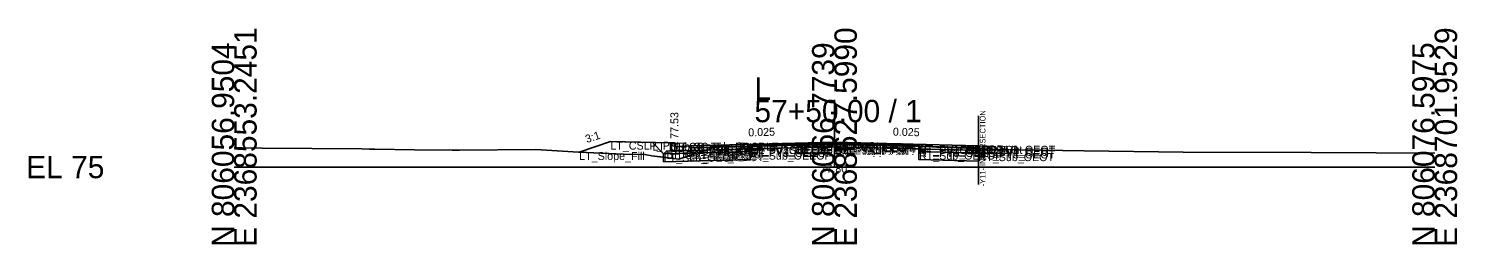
# Model space of a CAD drawing. Extents: x -26 to 8153, y -10 to 9520.
# Drawn here: x 4974.3 to 5152.8, y 5990.3 to 6017.3 of the extents above; entities that cross this region are included whole.
import ezdxf

# ---------------------------------------------------------------- set-up
doc = ezdxf.new("R2010")
doc.units = 0
for name, color, linetype in [('Exist CMT Pavement', 7, 'Continuous'), ('Exist Cross Section Cell', 7, 'Continuous'), ('Exist XS Center Line Elevation Label', 7, 'Continuous'), ('Exist XS Ground Line', 7, 'Continuous'), ('Prop CMT Conc Surface', 7, 'Continuous'), ('Prop CMT Concrete Structures', 7, 'Continuous'), ('Prop CMT Pvmt Course 1', 7, 'Continuous'), ('Prop CMT Pvmt Course 1 CG', 7, 'Continuous'), ('Prop CMT Pvmt Course 1 Wedge', 7, 'Continuous'), ('Prop CMT Pvmt Course 2', 7, 'Continuous'), ('Prop CMT Pvmt Course 2 Wedge', 7, 'Continuous'), ('Prop CMT Pvmt Course 3', 7, 'Continuous'), ('Prop CMT Pvmt Course 3 Wedge', 7, 'Continuous'), ('Prop CMT Pvmt Surface', 7, 'Continuous'), ('Prop CMT Pvmt Wedge Surface 1', 7, 'Continuous'), ('Prop CMT Pvmt Wedge Surface 2', 7, 'Continuous'), ('Prop CMT Pvmt Wedge Surface 3', 7, 'Continuous'), ('Prop CMT Shallow Undercut', 7, 'Continuous'), ('Prop CMT Shallow Undercut Boundary', 7, 'Continuous'), ('Prop CMT Shear Line', 7, 'Continuous'), ('Prop CMT Slope Grass', 7, 'Continuous'), ('Prop CMT Subgrade Earthwork', 7, 'Continuous'), ('Prop XS Earthwork Shape', 7, 'Continuous'), ('Prop XS Hydro Elevations', 7, 'Continuous'), ('Prop XS SE Text', 7, 'Continuous'), ('Prop XS Side Slope Text', 7, 'Continuous'), ('Prop XS Subgrade Earthwork', 7, 'Continuous'), ('Scratch_Level_2', 7, 'Continuous'), ('Scratch_Level_6', 7, 'Continuous')]:
    doc.layers.add(name, color=color, linetype=linetype)

msp = doc.modelspace()

# ---------------------------------------------------------------- linework, layer by layer
at = {"layer": 'Exist CMT Pavement'}
for p, q in [((5064.48, 6002.63), (5066.1, 6002.66)), ((5066.1, 6002.66), (5074.78, 6002.8)), ((5074.78, 6002.8), (5078.73, 6002.77)), ((5078.73, 6002.77), (5085.31, 6002.67))]:
    msp.add_line(p, q, dxfattribs=at)
at = {"layer": 'Exist Cross Section Cell'}
for p, q in [((5075, 6000), (5075, 6008.41)), ((5000, 6000), (5075, 6000)), ((5075, 6000), (5150, 6000))]:
    msp.add_line(p, q, dxfattribs=at)
at = {"layer": 'Exist XS Ground Line'}
for p, q in [((5000, 6002.42), (5000.99, 6002.42)), ((5000.99, 6002.42), (5003.48, 6002.38)), ((5003.48, 6002.38), (5015.93, 6002.26)), ((5058.92, 6002.13), (5060.23, 6002.58)), ((5060.23, 6002.58), (5062.69, 6002.58)), ((5062.69, 6002.58), (5064.48, 6002.63)), ((5064.48, 6002.63), (5066.1, 6002.66)), ((5066.1, 6002.66), (5074.78, 6002.8)), ((5074.78, 6002.8), (5078.73, 6002.77)), ((5078.73, 6002.77), (5085.31, 6002.67)), ((5085.31, 6002.67), (5087.81, 6002.49)), ((5087.81, 6002.49), (5092.95, 6002.31)), ((5092.95, 6002.31), (5095.38, 6002.21)), ((5015.93, 6002.26), (5016.91, 6002.23)), ((5016.91, 6002.23), (5017.57, 6002.22)), ((5017.57, 6002.22), (5022.53, 6002.16)), ((5022.53, 6002.16), (5027.22, 6002.11)), ((5027.22, 6002.11), (5028.16, 6002.11)), ((5028.16, 6002.11), (5037.68, 6002.19)), ((5037.68, 6002.19), (5043.04, 6001.88)), ((5043.04, 6001.88), (5048.64, 6001.63)), ((5048.64, 6001.63), (5051.31, 6001.57)), ((5051.31, 6001.57), (5052.19, 6001.39)), ((5052.19, 6001.39), (5055.56, 6000.99)), ((5055.56, 6000.99), (5058.92, 6002.13)), ((5095.38, 6002.21), (5106.22, 6002.01)), ((5106.22, 6002.01), (5118.56, 6001.88)), ((5118.56, 6001.88), (5134.55, 6001.8)), ((5134.55, 6001.8), (5142.7, 6001.77)), ((5142.7, 6001.77), (5150, 6001.75))]:
    msp.add_line(p, q, dxfattribs=at)
at = {"layer": 'Prop CMT Conc Surface'}
for points in [[(5055, 6002.53), (5055, 6003.03), (5054.5, 6003.03)], [(5057, 6002.66), (5055, 6002.53)]]:
    msp.add_lwpolyline(points, dxfattribs=at)
at = {"layer": 'Prop CMT Concrete Structures'}
for points in [[(5057, 6002.66), (5055, 6002.53), (5055, 6003.03), (5054.5, 6003.03)], [(5054.5, 6003.03), (5054.5, 6002.01), (5057, 6002.07)], [(5057, 6002.07), (5057, 6002.66)]]:
    msp.add_lwpolyline(points, dxfattribs=at)
at = {"layer": 'Prop CMT Pvmt Course 1'}
for points in [[(5075, 6003.11), (5057, 6002.66)], [(5057, 6002.66), (5057, 6002.41)], [(5057, 6002.41), (5064.48, 6002.59)], [(5064.48, 6002.72), (5075, 6002.98)], [(5064.48, 6002.59), (5064.48, 6002.72)], [(5075, 6002.86), (5075, 6003.11)], [(5075, 6003.11), (5093, 6002.66)], [(5075, 6002.86), (5075, 6003.11)], [(5075, 6002.98), (5075, 6002.86), (5075, 6002.86)], [(5085.56, 6002.72), (5075, 6002.98)], [(5075, 6002.98), (5075, 6002.86), (5075, 6002.86)], [(5085.56, 6002.59), (5085.56, 6002.72)], [(5093, 6002.41), (5085.56, 6002.59)], [(5093, 6002.66), (5093, 6002.41)]]:
    msp.add_lwpolyline(points, dxfattribs=at)
at = {"layer": 'Prop CMT Pvmt Course 1 CG'}
for points in [[(5057, 6002.07), (5054, 6002), (5053.66, 6001.66)], [(5053.66, 6001.66), (5057, 6001.74)], [(5057, 6001.74), (5057, 6002.07)]]:
    msp.add_lwpolyline(points, dxfattribs=at)
at = {"layer": 'Prop CMT Pvmt Course 1 Wedge'}
for points in [[(5075, 6002.98), (5064.48, 6002.72)], [(5075, 6002.98), (5085.56, 6002.72)]]:
    msp.add_lwpolyline(points, dxfattribs=at)
at = {"layer": 'Prop CMT Pvmt Course 2'}
for points in [[(5064.48, 6002.59), (5057, 6002.41)], [(5057, 6002.41), (5057, 6002.08)], [(5064.48, 6002.26), (5064.48, 6002.59)], [(5085.56, 6002.26), (5085.56, 6002.59)], [(5085.56, 6002.59), (5093, 6002.41)], [(5093, 6002.41), (5093, 6002.08)], [(5057, 6002.08), (5064.48, 6002.26)], [(5093, 6002.08), (5085.56, 6002.26)]]:
    msp.add_lwpolyline(points, dxfattribs=at)
at = {"layer": 'Prop CMT Pvmt Course 2 Wedge'}
for points in [[(5075, 6002.86), (5064.48, 6002.59)], [(5075, 6002.86), (5085.56, 6002.59)]]:
    msp.add_lwpolyline(points, dxfattribs=at)
at = {"layer": 'Prop CMT Pvmt Course 3'}
for points in [[(5064.48, 6002.26), (5057, 6002.08)], [(5057, 6002.08), (5057, 6001.74)], [(5057, 6001.74), (5064.48, 6001.93)], [(5064.48, 6001.93), (5064.48, 6002.26)], [(5085.56, 6002.26), (5093, 6002.08)], [(5085.56, 6001.93), (5085.56, 6002.26)], [(5093, 6001.74), (5085.56, 6001.93)], [(5093, 6002.08), (5093, 6001.74)]]:
    msp.add_lwpolyline(points, dxfattribs=at)
at = {"layer": 'Prop CMT Pvmt Course 3 Wedge'}
for points in [[(5075, 6002.53), (5064.48, 6002.26)], [(5075, 6002.53), (5085.56, 6002.26)]]:
    msp.add_lwpolyline(points, dxfattribs=at)
at = {"layer": 'Prop CMT Pvmt Surface'}
for points in [[(5075, 6003.11), (5057, 6002.66)], [(5075, 6003.11), (5093, 6002.66), (5093, 6002.31)]]:
    msp.add_lwpolyline(points, dxfattribs=at)
at = {"layer": 'Prop CMT Pvmt Wedge Surface 1'}
for points in [[(5057, 6002.41), (5057, 6002.66)], [(5064.48, 6002.59), (5057, 6002.41)], [(5075, 6002.98), (5064.48, 6002.72)], [(5064.48, 6002.72), (5064.48, 6002.59)], [(5075, 6002.98), (5085.56, 6002.72)], [(5085.56, 6002.72), (5085.56, 6002.59)], [(5085.56, 6002.59), (5093, 6002.41)], [(5093, 6002.41), (5093, 6002.66)]]:
    msp.add_lwpolyline(points, dxfattribs=at)
at = {"layer": 'Prop CMT Pvmt Wedge Surface 2'}
for points in [[(5075, 6002.86), (5057, 6002.41)], [(5057, 6002.41), (5057, 6002.66)], [(5075, 6002.86), (5093, 6002.41)], [(5093, 6002.41), (5093, 6002.66)]]:
    msp.add_lwpolyline(points, dxfattribs=at)
at = {"layer": 'Prop CMT Pvmt Wedge Surface 3'}
for points in [[(5057, 6002.08), (5057, 6002.66)], [(5075, 6002.53), (5057, 6002.08)], [(5075, 6002.53), (5093, 6002.08)], [(5093, 6002.08), (5093, 6002.66)]]:
    msp.add_lwpolyline(points, dxfattribs=at)
at = {"layer": 'Prop CMT Shallow Undercut'}
for p, q in [((5093, 6001.74), (5085.56, 6001.93)), ((5085.56, 6001.93), (5085.56, 6000.93)), ((5085.56, 6000.93), (5093, 6000.74)), ((5093, 6000.74), (5093, 6001.74))]:
    msp.add_line(p, q, dxfattribs=at)
msp.add_lwpolyline([(5053.66, 6001.22), (5053.66, 6000.66), (5064.48, 6000.93), (5064.48, 6001.93), (5057.84, 6001.76), (5055.56, 6000.99)], close=True, dxfattribs=at)
at = {"layer": 'Prop CMT Shallow Undercut Boundary'}
for p, q in [((5053.66, 6001.66), (5053.66, 6000.66)), ((5053.66, 6000.66), (5064.48, 6000.93)), ((5064.48, 6001.93), (5064.48, 6000.93)), ((5085.56, 6001.93), (5085.56, 6000.93)), ((5085.56, 6000.93), (5093, 6000.74)), ((5093, 6001.74), (5093, 6000.74))]:
    msp.add_line(p, q, dxfattribs=at)
at = {"layer": 'Prop CMT Shear Line'}
msp.add_line((5093, 5997.83), (5093, 6006.4), dxfattribs=at)
at = {"layer": 'Prop CMT Slope Grass'}
msp.add_lwpolyline([(5054.5, 6003.03), (5047, 6003.18), (5043.11, 6001.88)], dxfattribs=at)
at = {"layer": 'Prop CMT Subgrade Earthwork'}
for points in [[(5057, 6001.74), (5053.66, 6001.66), (5052.25, 6003.07)], [(5064.48, 6001.93), (5064.49, 6002.63)], [(5085.56, 6001.93), (5085.56, 6002.65)], [(5064.48, 6001.93), (5057, 6001.74)], [(5085.56, 6001.93), (5093, 6001.74)]]:
    msp.add_lwpolyline(points, dxfattribs=at)
at = {"layer": 'Prop XS Earthwork Shape'}
for points in [[(5053.66, 6001.66), (5053.66, 6001.22), (5052.19, 6001.39), (5051.31, 6001.57), (5048.64, 6001.63), (5043.11, 6001.88), (5047, 6003.18), (5052.25, 6003.07)], [(5064.48, 6001.93), (5057.84, 6001.76), (5058.92, 6002.13), (5060.23, 6002.58), (5062.69, 6002.58), (5064.48, 6002.63), (5064.49, 6002.63)], [(5064.48, 6001.93), (5057.84, 6001.76), (5055.56, 6000.99), (5053.66, 6001.22), (5053.66, 6000.66), (5064.48, 6000.93)], [(5057.84, 6001.76), (5057, 6001.74), (5053.66, 6001.66), (5053.66, 6001.22), (5055.56, 6000.99)], [(5085.56, 6001.93), (5085.56, 6000.93), (5093, 6000.74), (5093, 6001.74)], [(5085.56, 6001.93), (5085.56, 6000.93), (5093, 6000.74), (5093, 6001.74)]]:
    msp.add_lwpolyline(points, close=True, dxfattribs=at)
at = {"layer": 'Prop XS Subgrade Earthwork'}
for p, q in [((5053.66, 6001.66), (5064.48, 6001.93)), ((5085.56, 6001.93), (5093, 6001.74))]:
    msp.add_line(p, q, dxfattribs=at)
at = {"layer": 'Scratch_Level_6'}
for p, q in [((5093, 6001.74), (5085.56, 6001.93)), ((5085.56, 6001.93), (5085.56, 6000.93)), ((5085.56, 6000.93), (5093, 6000.74)), ((5093, 6000.74), (5093, 6001.74))]:
    msp.add_line(p, q, dxfattribs=at)
msp.add_lwpolyline([(5053.66, 6001.22), (5053.66, 6000.66), (5064.48, 6000.93), (5064.48, 6001.93), (5057.84, 6001.76), (5055.56, 6000.99)], close=True, dxfattribs=at)

# ---------------------------------------------------------------- texts
at = {"layer": 'Exist Cross Section Cell'}
for s, p in [('E 2368553.2451', (5002.8, 5990)), ('E 2368627.5990', (5077.8, 5990)), ('E 2368701.9529', (5152.8, 5990)), ('N 806056.9504', (5000, 5990)), ('N 806066.7739', (5075, 5990)), ('N 806076.5975', (5150, 5990))]:
    msp.add_text(s, height=2.8, rotation=90, dxfattribs=at).set_placement(p)
for s, p in [('L', (5065, 6008.41)), ('57+50.00 / 1', (5065, 6005.61)), ('EL 75', (4974, 5998.6))]:
    msp.add_text(s, height=2.8, dxfattribs=at).set_placement(p)
at = {"layer": 'Exist XS Center Line Elevation Label'}
msp.add_text('77.80', height=1, dxfattribs=at).set_placement((5073.25, 5999.3))
at = {"layer": 'Prop CMT Shear Line'}
msp.add_text('-Y11- INTERSECTION', height=0.7, rotation=90, dxfattribs=at).set_placement((5093.87, 5997.59))
at = {"layer": 'Prop XS Hydro Elevations'}
msp.add_text('77.53', height=1, rotation=90, dxfattribs=at).set_placement((5055.5, 6003.53))
at = {"layer": 'Prop XS SE Text'}
for rotation, p in [(1.4321, (5064.24, 6003.84)), (358.5679, (5082.29, 6003.93))]:
    msp.add_text('0.025', height=1, rotation=rotation, dxfattribs=at).set_placement(p)
at = {"layer": 'Prop XS Side Slope Text'}
msp.add_text('3:1', height=1, rotation=18.4349, dxfattribs=at).set_placement((5044.06, 6002.99))
at = {"layer": 'Scratch_Level_2'}
for s, p in [('LT_CSLP_Pnt', (5047, 6002.18)), ('LT_Sub_Trench_Out_DLT', (5052.25, 6002.07)), ('LT_CG_Top_BOC', (5054.5, 6002.03)), ('LT_CG_Top_Face', (5055, 6002.03)), ('LT_CG_Top_Gut', (5055, 6001.53)), ('LT_PV1_OEOT', (5057, 6001.66)), ('LT_PV2_OEOT', (5057, 6001.41)), ('LT_PV1_OEEOP', (5064.48, 6001.72)), ('LT_PV_OEEOP_EG', (5064.48, 6001.63)), ('LT_PV2_OEEOP', (5064.48, 6001.59)), ('LT_PV3_OEEOP', (5064.48, 6001.26)), ('LT_PV_Sub_Tie_Out', (5064.49, 6001.63)), ('PV1_PGL', (5075, 6002.11)), ('RT_PV1_IEEOP', (5075, 6001.98)), ('LT_PV1_IEEOP', (5075, 6001.98)), ('RT_PV2_IEEOP', (5075, 6001.86)), ('LT_PV2_IEEOP', (5075, 6001.86)), ('PV2_PGL', (5075, 6001.86)), ('RT_PV_IEEOP_EG', (5075, 6001.8)), ('LT_PV_IEEOP_EG', (5075, 6001.8)), ('RT_PV3_IEEOP', (5075, 6001.53)), ('LT_PV3_IEEOP', (5075, 6001.53)), ('RT_PV_Sub_Tie_Out', (5085.54, 6001.65)), ('RT_PV1_OEEOP', (5085.56, 6001.72)), ('RT_PV_OEEOP_EG', (5085.56, 6001.65)), ('RT_PV2_OEEOP', (5085.56, 6001.59)), ('RT_PV3_OEEOP', (5085.56, 6001.26)), ('RT_PV1_OEOT', (5093, 6001.66)), ('RT_PV2_OEOT', (5093, 6001.41)), ('LT_Slope_Fill', (5043.11, 6000.88)), ('LT_Sub_OEOP', (5053.66, 6000.66)), ('LT_CG1_Shelf_Out', (5054, 6001)), ('LT_CG_Bot_BOC', (5054.5, 6001.01)), ('LT_PV3_OEOT', (5057, 6001.08)), ('LT_CG_Bot_IE', (5057, 6001.07)), ('LT_Sub_OEOT', (5057, 6000.74)), ('LT_Sub_OEEOP', (5064.48, 6000.93)), ('RT_Sub_OEEOP', (5085.56, 6000.93)), ('RT_PV3_OEOT', (5093, 6001.08)), ('RT_Sub_OEOT', (5093, 6000.74))]:
    msp.add_text(s, height=1, dxfattribs=at).set_placement(p)

doc.saveas('drawing.dxf')
